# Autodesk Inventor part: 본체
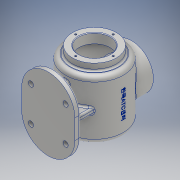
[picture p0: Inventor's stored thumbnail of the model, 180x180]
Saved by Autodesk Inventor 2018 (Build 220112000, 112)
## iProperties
Created: 2023-01
Part Number: 본체
Material: 알루미늄 6061
Document SubType Name: Modeling
Designer: home
Density: 2.7 g/cm^3
Appearance: 알루미늄 - 평지
Mass: 1034.39 g
Surface Area: 1157.53 cm^2
Volume: 383.109 cm^3
Author: home
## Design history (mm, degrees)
sketch "스케치1"
  geometry: L1 (0, 17)-(0, -17); L2 (-46, 17)-(-46, -17); L3 (46, -17)-(46, 17); C1 r 4.5 at (30, -30); C2 r 4.5 at (30, 30); C3 r 4.5 at (-30, 30); C4 r 4.5 at (-30, -30); A1 r 46 centre (0, 17) between (46, 17) and (-46, 17); A2 r 46 centre (0, -17) between (-46, -17) and (46, -17); 3 further points
  constraints: 8 end point, 6 centre point, 6 point on circle, 4 tangent, 1 equal radius, 1 midpoint, 1 parallel, 1 vertical
  dimensions: "d7" = 9 diameter of C2; "d8" = 9 diameter of C3; "d9" = 9 diameter of C4; "d18" = 60 distance of C1.centre C2.centre (derived); "d19" = 60 distance of C3.centre C2.centre (derived); "d22" = 92 distance between parallel lines of L2 L3; "d23" = 126 distance of point (0, -63) point (0, 63); "d140" = 16 distance from line of C2.centre L3; "d141" = 16 distance from line of C1.centre L3; "d142" = 76 distance from line of C3.centre L3; "d143" = 76 distance from line of C4.centre L3; "d144" = 42.42641 distance of C2.centre point (0, 0); "d145" = 42.42641 distance of C1.centre point (0, 0); "d146" = 42.42641 distance of C3.centre point (0, 0); "d147" = 42.42641 distance of C4.centre point (0, 0)
extrude "돌출1" new body sketch "스케치1" distance "d24" = 10; taper "d25" = 0 deg
node "작업 평면1"
sketch "스케치3"
  geometry: L1 (-27, 63)-(-38, 63); L2 (-38, 63)-(-38, 51); L3 (-38, 51)-(-50, 51); L4 (-27, 63)-(-27, 46); L5 (0, 0)-(0, 63); L6 (-50, 51)-(-50, -48.087); L7 (-45, -44.83)-(-45, 46); L8 (-45, 46)-(-27, 46); L9 (0, -59)-(0, -54); A1 r 120 centre (0, 61) between (-50, -48.087) and (0, -59); A2 r 115 centre (0, 61) between (-45, -44.83) and (0, -54)
  constraints: 18 end point, 5 vertical, 4 point on circle, 3 horizontal, 2 centre point, 1 other
  dimensions: "d30" = 38 distance of L5.end L1.end; "d31" = 12 distance of L1.end L2.end; "d34" = 17 distance of L1.start L4.end; "d55" = 120 radius of A1; "d56" = 122 distance from line of L9.start L1; "d58" = 59 distance of L9.start L5.start; "d59" = 100 diameter of L6 L5; "d60" = 5 radial gap between concentric circles of A1 A2; "d61" = 51 vertical distance of L5.start L2.end; "d62" = 54 diameter of L4 L5; "d63" = 76 diameter of L2 L5; "d64" = 0 distance from line of A1.centre L5
revolve "회전1" sketch "스케치3" stored, may be unused: angle "d65" = 90 deg
sketch "스케치4"
  geometry: L1 (-35, -5)-(0, -5); L2 (0, -5)-(35, -5); L3 (-35, 5)-(0, 5); L4 (0, 5)-(35, 5); L5 (-35, -5)-(-35, 5); L6 (35, -5)-(35, 5); 1 further point
  constraints: 12 end point, 2 vertical, 1 horizontal, 1 parallel
  dimensions: "d132" = 90 deg angle of L6 L3; "d133" = 90 deg angle of L6 L1; "d134" = 70 distance between parallel lines of L6 L5; "d135" = 10 distance between parallel lines of L2 L4; "d136" = 35 distance from line of point (0, 0) L6; "d137" = 5 distance from line of point (0, 0) L4; "d138" = 35 distance from line of L3.end L6; "d139" = 35 distance from line of L1.end L6
extrude "돌출2" join sketch "스케치4" stored distance "d70" = 10; taper "d71" = 0 deg
sketch "스케치5"
  geometry: L1 (10, 34.5)-(10, 25.5) reference; L2 (0, 17)-(0, 17) reference; L3 (0, 17)-(10, 17) reference; L4 (10, 17)-(10, 17) reference; L5 (0, 17)-(10, 17) reference; L6 (10, 40)-(30, 34.641); L7 (10, -17)-(10, 17) reference; L8 (10, -40)-(30, -34.641); L9 (10, -63)-(10, -17) reference; L10 (10, 17)-(10, 63) reference; L11 (30, -48.087)-(30, 51) reference; 1 further point
  constraints: 4 end point, 2 point on line
  dimensions: "d74" = 105 deg angle of L9 L8; "d75" = 23 distance of L10.end L6.start; "d76" = 80 distance of L8.start L6.start; "d77" = 105 deg angle of L10 L6; "d78" = 15.80156 distance from line of L11.end L6; "d79" = 82.72287 distance from line of L11.end L8
  node "투영된 루프1"
feature "리브1" dims "d80" = 1, "d81" = 10, "d82" = 0, "d83" = 0, "d84" = 1, "d85" = 1
feature "리브2" dims "d86" = 1, "d87" = 10, "d88" = 0, "d89" = 0, "d90" = 1, "d91" = 1
node "작업 평면2"
sketch "스케치6"
  geometry: L1 (38, 63)-(-38, 63) reference; C1 r 38 at (0, 0); 1 further point
  constraints: 1 centre point, 1 coincident
  dimensions: "d93" = 76 diameter of C1; "d94" = 63 distance from line of L1 point (0, 0) (derived)
extrude "돌출3" join sketch "스케치6" stored distance "d95" = 10; taper "d96" = 0 deg
sketch "스케치7"
  geometry: C1 r 27 at (0, 0); 1 further point
  constraints: 1 centre point, 1 coincident
  dimensions: "d97" = 54 diameter of C1
extrude "돌출4" cut sketch "스케치7" stored distance "d98" = 10; taper "d99" = 0 deg
sketch "스케치8" dims "d100" = 65
  geometry: L1 (-32.5, 0)-(0, 0); 1 further point
  constraints: 2 end point, 1 coincident, 1 horizontal, 1 horizontal alignment, 2 other
hole "구멍1" sketch "스케치8" at (-32.5, 0) diameter "d101" = 3.242; stored, may be unused: countersink angle "d105" = 90 deg, drill point angle "d107" = 118 deg; dims "d102" = 8, "d103" = 4, "d104" = 2, "d106" = 10
sketch "스케치9" dims "d111" = 65
  geometry: L1 (0, 0)-(0, 32.5); C1 r 38 at (0, 0) reference; C2 r 27 at (0, 0) reference; 1 further point
  constraints: 2 end point, 1 coincident, 1 vertical, 1 vertical alignment, 2 other
hole "구멍2" sketch "스케치9" at (0, 32.5) diameter "d112" = 3.242; stored, may be unused: countersink angle "d116" = 90 deg, drill point angle "d118" = 118 deg; dims "d113" = 8, "d114" = 4, "d115" = 2, "d117" = 10
chamfer "모따기1" distance "d122" = 1; stored, may be unused: second distance "d123" = 2, angle "d124" = 45 deg
fillet "모깎기1" dims "d125" = 8, "d126" = 3
node "작업 평면3"
sketch "스케치10" dims "d19" = 60 (derived)
  geometry: L1 (118, 63)-(42, 63) reference; L2 (0, -63)-(0, -17) reference; 3 further points
  constraints: 2 coincident, 1 other
  dimensions: "d128" = 63 distance from line of point (80, 0) L1; "d129" = 80 distance from line of L2 point (80, 0)
feature "엠보싱1" sketch "스케치10" dims "d7" = 9, "d8" = 9, "d9" = 9, "d18" = 60 (derived), "d19" = 60 (derived), "d22" = 92, "d23" = 126, "d130" = 0.5, "d131" = 0, "d140" = 16, "d141" = 16, "d142" = 76, "d143" = 76, "d144" = 42.42641, "d145" = 42.42641, "d146" = 42.42641, "d147" = 42.42641
node "솔리드1"
pattern_circular "원형 패턴1" dims angle "d109" = 360 deg
pattern_circular "원형 패턴2" dims angle "d120" = 360 deg
node "투영된 루프2"
other parameters: "d92" = -144, "d127" = 119
